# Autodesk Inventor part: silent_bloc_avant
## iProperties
Shininess: 64.0
Length Units: 11269
Angle Units: 11279
Time Units: 11290
Mass Units: 11283
Length Display Precision: 3
Angle Display Precision: 2
Compacted: True
Part Number: silent_bloc_avant
Document SubType Name: Modeling
Created: 2004-05
Material: Par défaut
Designer: David
Density: 0.0
Volumn: 0.0
Area: 0.0
PropertySet Name: Model Information
Control State: 0
Master: False
Checked Out: False
Author: David
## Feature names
1. Extrusion1
2. Extrusion2
3. Extrusion3
4. Extrusion4
5. Perçage1 [Hole]
